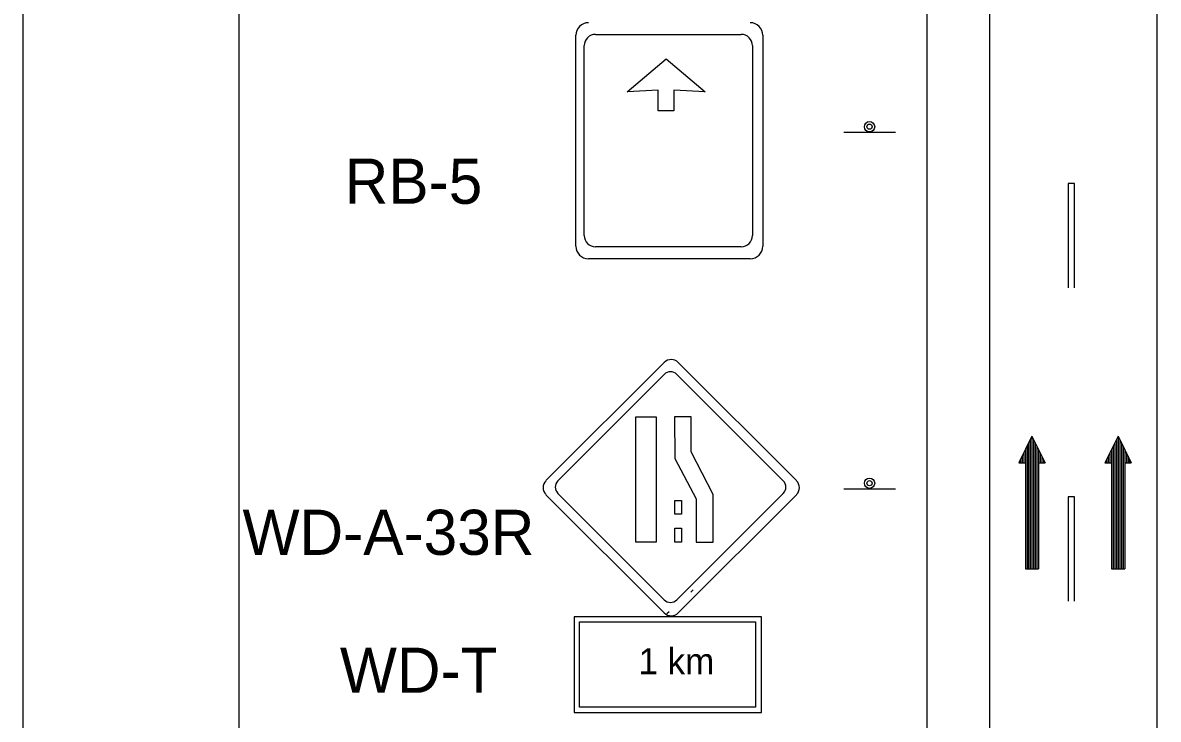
# Model space of a CAD drawing. Extents: x 2179 to 2395, y 134 to 413.
# Drawn here: x 2178.7 to 2231.3, y 199.9 to 232.2 of the extents above; entities that cross this region are included whole.
import ezdxf

# ---------------------------------------------------------------- set-up
doc = ezdxf.new("R2010")
doc.units = 0
for name, color, linetype in [('Level 1', 7, 'Continuous'), ('Level 10', 7, 'Continuous'), ('Level 2', 7, 'Continuous'), ('Level 44', 7, 'Continuous')]:
    doc.layers.add(name, color=color, linetype=linetype)

msp = doc.modelspace()

# ---------------------------------------------------------------- linework, layer by layer
at = {"layer": 'Level 1'}
for p, q in [((2227.137, 224.728), (2227.137, 219.89)), ((2227.427, 224.728), (2227.137, 224.728)), ((2227.137, 224.728), (2227.137, 219.89)), ((2227.427, 224.728), (2227.137, 224.728)), ((2227.427, 219.89), (2227.427, 224.728)), ((2227.427, 219.89), (2227.427, 224.728)), ((2227.137, 210.214), (2227.137, 205.376)), ((2227.427, 210.214), (2227.137, 210.214)), ((2227.137, 210.214), (2227.137, 205.376)), ((2227.427, 210.214), (2227.137, 210.214)), ((2227.427, 205.376), (2227.427, 210.214)), ((2227.427, 205.376), (2227.427, 210.214))]:
    msp.add_line(p, q, dxfattribs=at)
for points in [[(2394.748, 412.757), (2178.748, 412.757), (2178.748, 133.757), (2394.748, 133.757)], [(2375.622, 401.948), (2188.748, 401.948), (2188.748, 144.566), (2375.622, 144.566)]]:
    msp.add_lwpolyline(points, close=True, dxfattribs=at)
at = {"layer": 'Level 10'}
for p, q in [((2220.617, 223.004), (2220.617, 307.66)), ((2223.52, 223.009), (2223.52, 289.755)), ((2231.261, 223.022), (2231.261, 276.021)), ((2220.617, 173.333), (2220.617, 223.009)), ((2223.52, 173.382), (2223.52, 223.009)), ((2231.261, 173.432), (2231.261, 223.028)), ((2225.466, 213.022), (2224.852, 211.794)), ((2225.466, 213.022), (2225.466, 206.886)), ((2225.466, 213.022), (2226.079, 211.794)), ((2229.45, 213.022), (2228.837, 211.794)), ((2229.45, 213.022), (2229.45, 206.886)), ((2229.45, 213.022), (2230.063, 211.794)), ((2225.159, 212.408), (2225.159, 206.886)), ((2225.236, 212.561), (2225.236, 206.886)), ((2225.311, 212.714), (2225.311, 206.886)), ((2225.389, 212.868), (2225.389, 206.886)), ((2225.542, 212.868), (2225.542, 206.886)), ((2225.619, 212.714), (2225.619, 206.886)), ((2225.696, 212.561), (2225.696, 206.886)), ((2225.772, 212.408), (2225.772, 206.886)), ((2229.144, 212.408), (2229.144, 206.886)), ((2229.22, 212.561), (2229.22, 206.886)), ((2229.296, 212.714), (2229.296, 206.886)), ((2229.374, 212.868), (2229.374, 206.886)), ((2229.526, 212.868), (2229.526, 206.886)), ((2229.603, 212.714), (2229.603, 206.886)), ((2229.68, 212.561), (2229.68, 206.886)), ((2229.757, 212.408), (2229.757, 206.886)), ((2224.929, 211.948), (2224.929, 211.794)), ((2225.005, 212.101), (2225.005, 211.794)), ((2225.082, 212.255), (2225.082, 211.794)), ((2225.849, 212.255), (2225.849, 211.794)), ((2225.926, 212.101), (2225.926, 211.794)), ((2226.002, 211.948), (2226.002, 211.794)), ((2228.913, 211.948), (2228.913, 211.794)), ((2228.989, 212.101), (2228.989, 211.794)), ((2229.066, 212.255), (2229.066, 211.794)), ((2229.834, 212.255), (2229.834, 211.794)), ((2229.91, 212.101), (2229.91, 211.794)), ((2229.987, 211.948), (2229.987, 211.794)), ((2224.852, 211.794), (2225.159, 211.794)), ((2225.159, 211.794), (2225.159, 206.886)), ((2225.772, 211.794), (2225.772, 206.886)), ((2225.772, 211.794), (2226.079, 211.794)), ((2228.837, 211.794), (2229.144, 211.794)), ((2229.144, 211.794), (2229.144, 206.886)), ((2229.757, 211.794), (2229.757, 206.886)), ((2229.757, 211.794), (2230.063, 211.794)), ((2225.159, 206.886), (2225.772, 206.886)), ((2229.144, 206.886), (2229.757, 206.886))]:
    msp.add_line(p, q, dxfattribs=at)
for points in [[(2207.135, 213.91), (2208.07, 213.91), (2208.07, 208.12), (2207.135, 208.12)], [(2208.914, 213.91), (2208.926, 211.981), (2209.925, 210.123), (2209.925, 208.12), (2210.705, 208.12), (2210.705, 210.315), (2209.694, 212.294), (2209.694, 213.91)], [(2208.926, 210.047), (2209.239, 210.047), (2209.239, 209.405), (2208.926, 209.405)], [(2208.926, 208.762), (2209.239, 208.762), (2209.239, 208.12), (2208.926, 208.12)], [(2204.526, 204.425), (2212.669, 204.425), (2212.669, 200.471), (2204.526, 200.471)]]:
    msp.add_lwpolyline(points, close=True, dxfattribs=at)
at = {"layer": 'Level 2'}
for p, q in [((2209.783, 205.911), (2209.679, 205.807)), ((2208.669, 204.894), (2208.565, 204.79))]:
    msp.add_line(p, q, dxfattribs=at)
at = {"layer": 'Level 44'}
for p, q in [((2204.353, 221.816), (2204.353, 231.587)), ((2205.259, 231.626), (2212.005, 231.626)), ((2213.006, 231.587), (2213.006, 221.816)), ((2204.739, 222.311), (2204.739, 231.105)), ((2212.527, 231.105), (2212.527, 222.311)), ((2219.15, 227.081), (2216.754, 227.081)), ((2204.739, 222.309), (2204.739, 222.311)), ((2204.353, 221.813), (2204.353, 221.816)), ((2212.005, 221.789), (2205.259, 221.789)), ((2212.427, 221.235), (2204.931, 221.235)), ((2208.445, 216.433), (2202.967, 210.964)), ((2214.561, 210.964), (2209.092, 216.433)), ((2203.515, 210.959), (2208.445, 215.881)), ((2209.027, 215.881), (2213.951, 210.959)), ((2202.967, 210.314), (2208.445, 204.839)), ((2202.972, 210.314), (2202.967, 210.314)), ((2208.445, 205.448), (2203.515, 210.374)), ((2213.951, 210.374), (2209.027, 205.448)), ((2209.092, 204.839), (2214.561, 210.314)), ((2219.15, 210.576), (2216.754, 210.576))]:
    msp.add_line(p, q, dxfattribs=at)
for points in [[(2206.72, 228.971), (2208.529, 230.494), (2210.339, 228.971), (2208.891, 229.047), (2208.891, 228.082), (2208.167, 228.082), (2208.167, 229.047)], [(2212.944, 204.657), (2204.28, 204.657), (2204.28, 200.229), (2212.944, 200.229)]]:
    msp.add_lwpolyline(points, close=True, dxfattribs=at)
for centre, radius in [((2217.947, 227.35), 0.24), ((2217.947, 227.35), 0.12), ((2217.947, 210.844), 0.24), ((2217.947, 210.844), 0.12)]:
    msp.add_circle(centre, radius, dxfattribs=at)
for centre, radius, start, end in [((2204.932, 231.586), 0.578, 90, 180), ((2212.427, 231.586), 0.578, 360, 90), ((2205.26, 231.104), 0.52, 90, 180), ((2212.005, 231.104), 0.52, 360, 90), ((2205.26, 222.309), 0.52, 180, 270), ((2212.005, 222.309), 0.52, 270, 360), ((2204.932, 221.814), 0.578, 180, 270), ((2212.427, 221.814), 0.578, 270, 360), ((2208.767, 216.111), 0.458, 45, 135), ((2208.735, 215.592), 0.412, 45, 135), ((2203.295, 210.638), 0.458, 135, 225), ((2203.81, 210.666), 0.412, 135, 225), ((2213.66, 210.666), 0.412, 315, 45), ((2214.24, 210.638), 0.458, 315, 45), ((2208.735, 205.741), 0.412, 225, 315), ((2208.767, 205.166), 0.458, 225, 315)]:
    msp.add_arc(centre, radius, start, end, dxfattribs=at)

# ---------------------------------------------------------------- texts
at = {"layer": 'Level 1'}
msp.add_text('WD-T', height=2.09, dxfattribs=at).set_placement((2193.43, 201.141))
at = {"layer": 'Level 10'}
for s, p in [('RB-5', (2193.654, 223.782)), ('WD-A-33R', (2188.924, 207.527))]:
    msp.add_text(s, height=2.09, dxfattribs=at).set_placement(p)
at = {"layer": 'Level 44'}
msp.add_text('1 km', height=1.2095, dxfattribs=at).set_placement((2207.252, 201.997))

doc.saveas('drawing.dxf')
